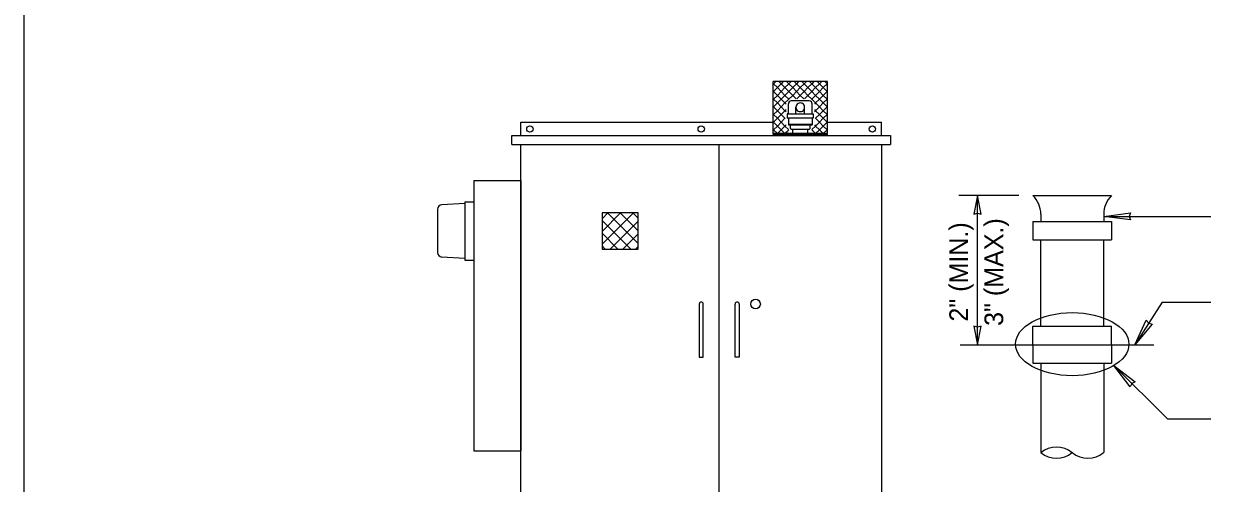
# Model space of a CAD drawing. Extents: x 99862 to 103151, y 100000 to 117076.
# Drawn here: x 99862 to 100882, y 103698 to 104090 of the extents above; entities that cross this region are included whole.
import ezdxf

# ---------------------------------------------------------------- set-up
doc = ezdxf.new("R2010")
doc.units = 0
for name, color, linetype in [('Level 1', 7, 'Continuous'), ('Level 15', 7, 'Continuous'), ('Level 20', 7, 'Continuous'), ('Level 40', 7, 'Continuous')]:
    doc.layers.add(name, color=color, linetype=linetype)

msp = doc.modelspace()

# ---------------------------------------------------------------- linework, layer by layer
at = {"layer": 'Level 1'}
for p, q in [((100501.9, 103996.5), (100501.9, 104040.9)), ((100548.1, 104040.9), (100501.9, 104040.9)), ((100502.1, 104039), (100504, 104040.9)), ((100506.7, 104040.9), (100508.6, 104039)), ((100510.5, 104040.9), (100508.6, 104039)), ((100515.2, 104039), (100513.3, 104040.9)), ((100517.1, 104040.9), (100515.2, 104039)), ((100521.7, 104039), (100519.8, 104040.9)), ((100523.6, 104040.9), (100521.7, 104039)), ((100528.3, 104039), (100526.4, 104040.9)), ((100530.2, 104040.9), (100528.3, 104039)), ((100534.8, 104039), (100532.9, 104040.9)), ((100536.7, 104040.9), (100534.8, 104039)), ((100539.5, 104040.9), (100541.4, 104039)), ((100541.4, 104039), (100543.3, 104040.9)), ((100547.9, 104039), (100546, 104040.9)), ((100548.1, 103996.5), (100548.1, 104040.9)), ((100501.9, 104039.2), (100502.1, 104039)), ((100502.1, 104039), (100501.9, 104038.9)), ((100501.9, 104032.7), (100502.1, 104032.5)), ((100502.1, 104032.5), (100501.9, 104032.3)), ((100505.4, 104035.8), (100502.1, 104039)), ((100502.1, 104032.5), (100505.4, 104035.8)), ((100505.4, 104029.2), (100502.1, 104032.5)), ((100508.6, 104039), (100505.4, 104035.8)), ((100505.4, 104035.8), (100508.6, 104032.5)), ((100508.6, 104032.5), (100505.4, 104029.2)), ((100508.6, 104039), (100511.9, 104035.8)), ((100511.9, 104035.8), (100508.6, 104032.5)), ((100508.6, 104032.5), (100511.9, 104029.2)), ((100511.9, 104035.8), (100515.2, 104039)), ((100515.2, 104032.5), (100511.9, 104035.8)), ((100511.9, 104029.2), (100515.2, 104032.5)), ((100515.2, 104039), (100518.5, 104035.8)), ((100518.5, 104035.8), (100515.2, 104032.5)), ((100515.2, 104032.5), (100518.5, 104029.2)), ((100518.5, 104035.8), (100521.7, 104039)), ((100521.7, 104032.5), (100518.5, 104035.8)), ((100518.5, 104029.2), (100521.7, 104032.5)), ((100521.7, 104039), (100525, 104035.8)), ((100525, 104035.8), (100521.7, 104032.5)), ((100521.7, 104032.5), (100525, 104029.2)), ((100525, 104035.8), (100528.3, 104039)), ((100528.3, 104032.5), (100525, 104035.8)), ((100525, 104029.2), (100528.3, 104032.5)), ((100528.3, 104039), (100531.5, 104035.8)), ((100531.5, 104035.8), (100528.3, 104032.5)), ((100528.3, 104032.5), (100531.5, 104029.2)), ((100531.5, 104035.8), (100534.8, 104039)), ((100534.8, 104032.5), (100531.5, 104035.8)), ((100531.5, 104029.2), (100534.8, 104032.5)), ((100534.8, 104039), (100538.1, 104035.8)), ((100538.1, 104035.8), (100534.8, 104032.5)), ((100534.8, 104032.5), (100538.1, 104029.2)), ((100538.1, 104035.8), (100541.4, 104039)), ((100541.4, 104032.5), (100538.1, 104035.8)), ((100538.1, 104029.2), (100541.4, 104032.5)), ((100541.4, 104039), (100544.6, 104035.8)), ((100544.6, 104035.8), (100541.4, 104032.5)), ((100541.4, 104032.5), (100544.6, 104029.2)), ((100544.6, 104035.8), (100547.9, 104039)), ((100547.9, 104032.5), (100544.6, 104035.8)), ((100544.6, 104029.2), (100547.9, 104032.5)), ((100548.1, 104039.2), (100547.9, 104039)), ((100547.9, 104039), (100548.1, 104038.9)), ((100548.1, 104032.7), (100547.9, 104032.5)), ((100547.9, 104032.5), (100548.1, 104032.3)), ((100501.9, 104026.1), (100502.1, 104025.9)), ((100502.1, 104025.9), (100501.9, 104025.8)), ((100501.9, 104019.6), (100502.1, 104019.4)), ((100502.1, 104019.4), (100501.9, 104019.2)), ((100502.1, 104025.9), (100505.4, 104029.2)), ((100505.4, 104022.7), (100502.1, 104025.9)), ((100502.1, 104019.4), (100505.4, 104022.7)), ((100505.4, 104016.1), (100502.1, 104019.4)), ((100505.4, 104029.2), (100508.6, 104025.9)), ((100508.6, 104025.9), (100505.4, 104022.7)), ((100505.4, 104022.7), (100508.6, 104019.4)), ((100508.6, 104019.4), (100505.4, 104016.1)), ((100511.9, 104029.2), (100508.6, 104025.9)), ((100508.6, 104025.9), (100511.9, 104022.7)), ((100511.9, 104022.7), (100508.6, 104019.4)), ((100508.6, 104019.4), (100511.9, 104016.1)), ((100515.2, 104025.9), (100511.9, 104029.2)), ((100511.9, 104022.7), (100515.2, 104025.9)), ((100513, 104021.6), (100511.9, 104022.7)), ((100514.8, 104013.3), (100514.8, 104021.9)), ((100518.5, 104029.2), (100515.2, 104025.9)), ((100515.2, 104025.9), (100515.3, 104025.8)), ((100532.7, 104024.4), (100517.3, 104024.4)), ((100521.4, 104026.2), (100518.5, 104029.2)), ((100525, 104029.2), (100522, 104026.2)), ((100528, 104026.2), (100525, 104029.2)), ((100531.5, 104029.2), (100528.6, 104026.2)), ((100534.8, 104025.9), (100531.5, 104029.2)), ((100534.7, 104025.8), (100534.8, 104025.9)), ((100538.1, 104029.2), (100534.8, 104025.9)), ((100534.8, 104025.9), (100538.1, 104022.7)), ((100535.2, 104013.3), (100535.2, 104021.9)), ((100538.1, 104022.7), (100537, 104021.6)), ((100541.4, 104025.9), (100538.1, 104029.2)), ((100538.1, 104022.7), (100541.4, 104025.9)), ((100541.4, 104019.4), (100538.1, 104022.7)), ((100538.1, 104016.1), (100541.4, 104019.4)), ((100544.6, 104029.2), (100541.4, 104025.9)), ((100541.4, 104025.9), (100544.6, 104022.7)), ((100544.6, 104022.7), (100541.4, 104019.4)), ((100541.4, 104019.4), (100544.6, 104016.1)), ((100547.9, 104025.9), (100544.6, 104029.2)), ((100544.6, 104022.7), (100547.9, 104025.9)), ((100547.9, 104019.4), (100544.6, 104022.7)), ((100544.6, 104016.1), (100547.9, 104019.4)), ((100548.1, 104026.1), (100547.9, 104025.9)), ((100547.9, 104025.9), (100548.1, 104025.8)), ((100548.1, 104019.6), (100547.9, 104019.4)), ((100547.9, 104019.4), (100548.1, 104019.2)), ((100501.9, 104013), (100502.1, 104012.8)), ((100502.1, 104012.8), (100501.9, 104012.7)), ((100502.1, 104012.8), (100505.4, 104016.1)), ((100505.4, 104009.6), (100502.1, 104012.8)), ((100502.1, 104006.3), (100505.4, 104009.6)), ((100505.4, 104016.1), (100508.6, 104012.8)), ((100508.6, 104012.8), (100505.4, 104009.6)), ((100505.4, 104009.6), (100508.6, 104006.3)), ((100511.9, 104016.1), (100508.6, 104012.8)), ((100508.6, 104012.8), (100511.9, 104009.6)), ((100511.9, 104009.6), (100508.6, 104006.3)), ((100511.9, 104016.1), (100513, 104017.2)), ((100512.9, 104015.1), (100511.9, 104016.1)), ((100511.9, 104009.6), (100512, 104009.7)), ((100512, 104009.4), (100511.9, 104009.6)), ((100514.8, 104013.3), (100513.9, 104013.3)), ((100513.9, 104013.3), (100513.9, 104009.6)), ((100536.1, 104009.6), (100513.9, 104009.6)), ((100514.8, 104013.3), (100535.2, 104013.3)), ((100514.8, 104009.6), (100514.8, 104004)), ((100521.3, 104013.3), (100521.3, 104019)), ((100528.7, 104013.3), (100528.7, 104019)), ((100535.2, 104013.3), (100536.1, 104013.3)), ((100535.2, 104009.6), (100535.2, 104004)), ((100536.1, 104013.3), (100536.1, 104009.6)), ((100537, 104017.2), (100538.1, 104016.1)), ((100538.1, 104016.1), (100537.1, 104015.1)), ((100538, 104009.7), (100538.1, 104009.6)), ((100538.1, 104009.6), (100538, 104009.4)), ((100541.4, 104012.8), (100538.1, 104016.1)), ((100538.1, 104009.6), (100541.4, 104012.8)), ((100541.4, 104006.3), (100538.1, 104009.6)), ((100544.6, 104016.1), (100541.4, 104012.8)), ((100541.4, 104012.8), (100544.6, 104009.6)), ((100544.6, 104009.6), (100541.4, 104006.3)), ((100547.9, 104012.8), (100544.6, 104016.1)), ((100544.6, 104009.6), (100547.9, 104012.8)), ((100547.9, 104006.3), (100544.6, 104009.6)), ((100548.1, 104013), (100547.9, 104012.8)), ((100547.9, 104012.8), (100548.1, 104012.7)), ((100501.9, 104006.5), (100502.1, 104006.3)), ((100502.1, 104006.3), (100501.9, 104006.1)), ((100501.9, 103999.9), (100502.1, 103999.8)), ((100502.1, 103999.8), (100501.9, 103999.6)), ((100505.4, 104003), (100502.1, 104006.3)), ((100502.1, 103999.8), (100505.4, 104003)), ((100505.4, 103996.5), (100502.1, 103999.8)), ((100508.6, 104006.3), (100505.4, 104003)), ((100505.4, 104003), (100508.6, 103999.8)), ((100508.6, 103999.8), (100505.4, 103996.5)), ((100508.6, 104006.3), (100511.9, 104003)), ((100511.9, 104003), (100508.6, 103999.8)), ((100508.6, 103999.8), (100511.9, 103996.5)), ((100511.9, 104003), (100513, 104004.1)), ((100515, 104000), (100511.9, 104003)), ((100511.9, 103996.5), (100515.1, 103999.7)), ((100514.8, 104004.5), (100535.2, 104004.5)), ((100514.8, 104004), (100535.2, 104004)), ((100516.7, 104000.8), (100516.7, 104004)), ((100517.1, 104000.3), (100532.9, 104000.3)), ((100518.5, 103996.6), (100518.5, 104000.3)), ((100531.5, 103996.6), (100531.5, 104000.3)), ((100533.3, 104000.8), (100533.3, 104004)), ((100534.9, 103999.7), (100538.1, 103996.5)), ((100538.1, 104003), (100535, 104000)), ((100537, 104004.1), (100538.1, 104003)), ((100538.1, 104003), (100541.4, 104006.3)), ((100541.4, 103999.8), (100538.1, 104003)), ((100538.1, 103996.5), (100541.4, 103999.8)), ((100541.4, 104006.3), (100544.6, 104003)), ((100544.6, 104003), (100541.4, 103999.8)), ((100541.4, 103999.8), (100544.6, 103996.5)), ((100544.6, 104003), (100547.9, 104006.3)), ((100547.9, 103999.8), (100544.6, 104003)), ((100544.6, 103996.5), (100547.9, 103999.8)), ((100548.1, 104006.5), (100547.9, 104006.3)), ((100547.9, 104006.3), (100548.1, 104006.1)), ((100548.1, 103999.9), (100547.9, 103999.8)), ((100547.9, 103999.8), (100548.1, 103999.6)), ((100548.1, 103996.5), (100501.9, 103996.5)), ((100501.9, 103995.7), (100501.9, 103996.4)), ((100548.1, 103996.4), (100501.9, 103996.4)), ((100548.1, 103995.7), (100501.9, 103995.7)), ((100520.4, 103994.8), (100529.6, 103994.8)), ((100548.1, 103995.7), (100548.1, 103996.4)), ((100246.1, 103956.3), (100286.5, 103956.3)), ((100246.1, 103956.3), (100246.1, 103725.4)), ((100286.5, 103956.3), (100286.5, 103725.4)), ((100238.4, 103938.3), (100246.1, 103938.3)), ((100238.4, 103938.3), (100238.4, 103888.3)), ((100723.7, 103943.5), (100790.8, 103943.5)), ((100215.3, 103931.8), (100215.3, 103894.9)), ((100238.4, 103936.8), (100218.9, 103935.6)), ((100730.4, 103927.7), (100730.4, 103921.5)), ((100784.1, 103927.7), (100784.1, 103921.5)), ((100723.7, 103921.5), (100723.7, 103905.7)), ((100723.7, 103921.5), (100790.8, 103921.5)), ((100790.8, 103921.5), (100790.8, 103905.7)), ((100723.7, 103905.7), (100790.8, 103905.7)), ((100730.4, 103832), (100730.4, 103905.7)), ((100784.1, 103832), (100784.1, 103905.7)), ((100238.4, 103889.9), (100218.9, 103891)), ((100238.4, 103888.3), (100246.1, 103888.3)), ((100438.6, 103850.9), (100438.6, 103848.6)), ((100438.6, 103848.6), (100438.6, 103805.4)), ((100442.1, 103848.6), (100442.1, 103850.9)), ((100442.1, 103805.4), (100442.1, 103848.6)), ((100469.4, 103848.6), (100469.4, 103850.9)), ((100469.4, 103805.4), (100469.4, 103848.6)), ((100472.8, 103850.9), (100472.8, 103848.6)), ((100472.8, 103848.6), (100472.8, 103805.4)), ((100723.7, 103816.1), (100723.7, 103832)), ((100723.7, 103832), (100790.8, 103832)), ((100790.8, 103816.1), (100790.8, 103832)), ((100723.7, 103816.1), (100723.7, 103800.3)), ((100790.8, 103816.1), (100790.8, 103800.3)), ((100438.6, 103805.4), (100442.1, 103805.4)), ((100472.8, 103805.4), (100469.4, 103805.4)), ((100723.7, 103800.3), (100790.8, 103800.3)), ((100730.4, 103800.3), (100730.4, 103723.9)), ((100784.1, 103800.3), (100784.1, 103723.9)), ((100246.1, 103725.4), (100286.5, 103725.4))]:
    msp.add_line(p, q, dxfattribs=at)
msp.add_lwpolyline([(99862, 102999.5), (103151, 102999.5), (103151, 105075.5), (99862, 105075.5)], close=True, dxfattribs=at)
msp.add_circle((100486.8, 103850.9), 4.11, dxfattribs=at)
for centre, radius, start, end in [((100517.3, 104021.9), 2.47, 90, 180), ((100525, 104019), 3.7, 359.9997, 180), ((100532.7, 104021.9), 2.47, 0, 90), ((100525, 104019), 3.7, 180, 0.0003), ((100517.1, 104000.8), 0.463, 180, 270), ((100532.9, 104000.8), 0.463, 270, 0), ((100520.4, 103996.6), 1.85, 180, 270), ((100529.6, 103996.6), 1.85, 270, 0), ((100708.4, 103927.7), 22, 0, 45.9402), ((100806.1, 103927.7), 22, 134.0598, 180), ((100219.1, 103931.8), 3.85, 93.3424, 180), ((100219.1, 103894.9), 3.85, 180, 266.6576), ((100440.4, 103850.9), 1.71, 0, 180), ((100471.1, 103850.9), 1.71, 0, 180), ((100743.8, 103707.4), 21.2, 50.8329, 129.1671), ((100743.8, 103740.4), 21.2, 230.8329, 309.1671), ((100770.6, 103740.4), 21.2, 230.8329, 309.1671)]:
    msp.add_arc(centre, radius, start, end, dxfattribs=at)
at = {"layer": 'Level 15'}
for p, q in [((100278.8, 103994.8), (100601.9, 103994.8)), ((100278.8, 103987.1), (100278.8, 103994.8)), ((100601.9, 103994.8), (100601.9, 103987.1)), ((100278.8, 103987.1), (100601.9, 103987.1)), ((100711.7, 103943.5), (100660.3, 103943.5)), ((100676.3, 103816.1), (100676.3, 103943.5)), ((100784.1, 103925.8), (100875.6, 103925.8)), ((100834, 103852.5), (100810.7, 103816.1)), ((100834, 103852.5), (100875.6, 103852.5)), ((100792.8, 103798.3), (100838.5, 103752.7)), ((100838.5, 103752.7), (100875.6, 103752.7))]:
    msp.add_line(p, q, dxfattribs=at)
for points in [[(100676.3, 103943.5), (100673.2, 103927.8), (100676.3, 103928.5), (100679.4, 103927.8)], [(100784.1, 103925.8), (100806.9, 103928.8), (100805.8, 103925.8), (100806.9, 103922.8)], [(100810.7, 103816.1), (100820.5, 103837), (100822.5, 103834.5), (100825.6, 103833.7)], [(100676.3, 103816.1), (100679.4, 103831.9), (100676.3, 103831.1), (100673.2, 103831.9)], [(100792.8, 103798.3), (100811.1, 103784.3), (100808.2, 103782.9), (100806.8, 103780)]]:
    msp.add_lwpolyline(points, close=True, dxfattribs=at)
for centre in [(100294.1, 104000.5), (100440.4, 104000.5), (100586.6, 104000.5)]:
    msp.add_circle(centre, 2.69, dxfattribs=at)
msp.add_ellipse((100757.2, 103816.6), major_axis=(48.4, 0), ratio=0.556705, dxfattribs=at)
at = {"layer": 'Level 40'}
for p, q in [((100286.5, 104006.3), (100501.9, 104006.3)), ((100286.5, 103994.8), (100286.5, 104006.3)), ((100548.1, 104006.3), (100594.3, 104006.3)), ((100594.3, 103994.8), (100594.3, 104006.3)), ((100286.5, 103994.8), (100594.3, 103994.8)), ((100286.5, 103675.4), (100286.5, 103987.1)), ((100455.7, 103687), (100455.7, 103987.1)), ((100594.3, 103987.1), (100594.3, 103675.4)), ((100355.7, 103901.9), (100382.5, 103928.7)), ((100355.7, 103912.8), (100371.6, 103928.7)), ((100355.7, 103923.7), (100360.7, 103928.7)), ((100360.3, 103928.7), (100386.5, 103902.5)), ((100371.2, 103928.7), (100386.5, 103913.4)), ((100382, 103928.7), (100386.5, 103924.3)), ((100355.7, 103922.4), (100380.2, 103897.9)), ((100362.6, 103897.9), (100386.5, 103921.8)), ((100355.7, 103911.5), (100369.3, 103897.9)), ((100373.5, 103897.9), (100386.5, 103911)), ((100355.7, 103900.6), (100358.4, 103897.9)), ((100384.4, 103897.9), (100386.5, 103900.1)), ((100661.4, 103816.1), (100827, 103816.1))]:
    msp.add_line(p, q, dxfattribs=at)
for points in [[(100514.9, 103995.1), (100514.9, 103994.9), (100512.9, 103994.9), (100512.9, 103995.1)], [(100514.9, 103994.9), (100514.9, 103994.8), (100512.9, 103994.8), (100512.9, 103994.9)], [(100514.6, 103996.4), (100514.6, 103997), (100513.1, 103997), (100513.1, 103996.4)], [(100514.6, 103995.1), (100514.6, 103995.7), (100513.1, 103995.7), (100513.1, 103995.1)], [(100535.1, 103995.1), (100535.1, 103994.9), (100537.1, 103994.9), (100537.1, 103995.1)], [(100535.1, 103994.9), (100535.1, 103994.8), (100537.1, 103994.8), (100537.1, 103994.9)], [(100535.4, 103996.4), (100535.4, 103997), (100536.9, 103997), (100536.9, 103996.4)], [(100535.4, 103995.1), (100535.4, 103995.7), (100536.9, 103995.7), (100536.9, 103995.1)], [(100355.7, 103897.9), (100386.5, 103897.9), (100386.5, 103928.7), (100355.7, 103928.7)]]:
    msp.add_lwpolyline(points, close=True, dxfattribs=at)

# ---------------------------------------------------------------- texts
at = {"layer": 'Level 20'}
for s, p in [('2" (MIN.)', (100668.3, 103835.9)), ('3" (MAX.)', (100698.3, 103832.2))]:
    msp.add_text(s, height=16, rotation=90, dxfattribs=at).set_placement(p)

doc.saveas('drawing.dxf')
